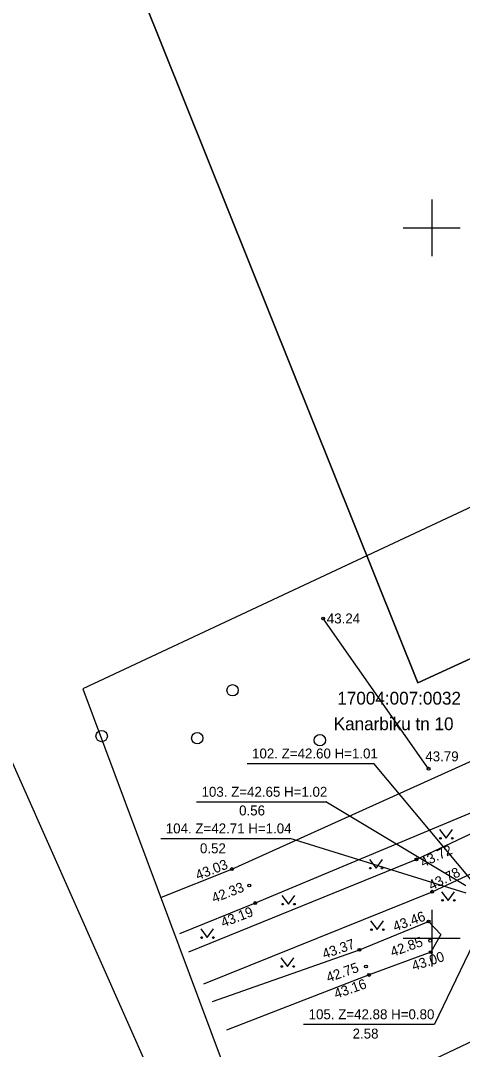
# Model space of a CAD drawing. Extents: x 642747 to 644424, y 6457048 to 6458238.
# Drawn here: x 643521.1 to 643552.2, y 6457442.2 to 6457514.6 of the extents above; entities that cross this region are included whole.
import ezdxf

# ---------------------------------------------------------------- set-up
doc = ezdxf.new("R2010")
doc.units = 0
for name, color, linetype in [('HALJASTUS', 7, 'Continuous'), ('JOONSIDE', 7, 'Continuous'), ('KOORDPUNKT', 7, 'Continuous'), ('KORGUS', 7, 'Continuous'), ('MOOTPIIR', 7, 'Continuous'), ('PIIR', 7, 'Continuous'), ('TEE', 7, 'Continuous'), ('VEEKOGU', 7, 'Continuous'), ('VORK', 7, 'Continuous'), ('VORMISTUS', 7, 'Continuous')]:
    doc.layers.add(name, color=color, linetype=linetype)

msp = doc.modelspace()

# ---------------------------------------------------------------- linework, layer by layer
at = {"layer": 'HALJASTUS'}
for p, q in [((643549.784, 6457461.931), (643542.364, 6457472.504)), ((643550.56, 6457457.643), (643551.024, 6457457.036)), ((643551.024, 6457457.036), (643551.469, 6457457.643)), ((643545.621, 6457455.54), (643546.085, 6457454.933)), ((643546.085, 6457454.933), (643546.53, 6457455.54)), ((643539.454, 6457453.001), (643539.918, 6457452.394)), ((643539.918, 6457452.394), (643540.363, 6457453.001)), ((643550.697, 6457453.264), (643551.161, 6457452.658)), ((643551.161, 6457452.658), (643551.606, 6457453.264)), ((643545.701, 6457451.213), (643546.165, 6457450.606)), ((643546.165, 6457450.606), (643546.61, 6457451.213)), ((643533.751, 6457450.653), (643534.215, 6457450.046)), ((643534.215, 6457450.046), (643534.66, 6457450.653)), ((643539.398, 6457448.619), (643539.861, 6457448.012)), ((643539.861, 6457448.012), (643540.307, 6457448.619))]:
    msp.add_line(p, q, dxfattribs=at)
for centre, radius in [((643535.994, 6457467.447), 0.4), ((643526.781, 6457464.228), 0.4), ((643533.508, 6457464.081), 0.4), ((643542.136, 6457463.935), 0.4), ((643550.622, 6457457.036), 0.055), ((643551.451, 6457457.036), 0.055), ((643545.683, 6457454.933), 0.055), ((643546.512, 6457454.933), 0.055), ((643539.517, 6457452.394), 0.055), ((643540.345, 6457452.394), 0.055), ((643550.76, 6457452.658), 0.055), ((643551.588, 6457452.658), 0.055), ((643533.814, 6457450.046), 0.055), ((643534.642, 6457450.046), 0.055), ((643545.764, 6457450.606), 0.055), ((643546.592, 6457450.606), 0.055), ((643539.46, 6457448.012), 0.055), ((643540.289, 6457448.012), 0.055)]:
    msp.add_circle(centre, radius, dxfattribs=at)
at = {"layer": 'KOORDPUNKT'}
for p, q in [((643537.014, 6457462.3), (643545.938, 6457462.3)), ((643552.787, 6457454.11), (643545.938, 6457462.3)), ((643533.46, 6457459.604), (643542.56, 6457459.604)), ((643552.412, 6457453.688), (643542.56, 6457459.604)), ((643530.943, 6457457.027), (643540.042, 6457457.027)), ((643552.422, 6457453.169), (643540.042, 6457457.027)), ((643553.504, 6457450.823), (643550.197, 6457443.946)), ((643540.993, 6457443.946), (643550.197, 6457443.946))]:
    msp.add_line(p, q, dxfattribs=at)
at = {"layer": 'KORGUS'}
for centre in [(643542.364, 6457472.504), (643549.784, 6457461.931), (643548.923, 6457455.546), (643535.943, 6457454.867), (643537.169, 6457453.715), (643550.034, 6457453.271), (643537.582, 6457452.477), (643549.783, 6457451.173), (643549.902, 6457449.827), (643544.915, 6457449.187), (643549.93, 6457449.018), (643545.378, 6457448.014), (643545.596, 6457447.416)]:
    msp.add_circle(centre, 0.1, dxfattribs=at)
at = {"layer": 'MOOTPIIR'}
msp.add_lwpolyline([(643525.446, 6457467.559), (643537.447, 6457435.458), (643944.848, 6457628.51), (644046.626, 6457529.09), (644067.022, 6457529.09), (644138.408, 6457598.401), (644075.1, 6457775.215), (644046.02, 6457752.582), (644092.466, 6457611.94), (644070.657, 6457576.375), (644041.981, 6457570.717), (643942.223, 6457662.862)], close=True, dxfattribs=at)
at = {"layer": 'PIIR'}
for points in [[(643435.34, 6457542.04), (643098.5, 6457289.43), (643172.06, 6457253.87), (643223.42, 6457347.01), (643584.12, 6457368.52), (643583, 6457371.27), (643552.96, 6457445.6), (643559.88, 6457465.04), (643557.62, 6457471.91), (643549.02, 6457467.97), (643522.25, 6457534.76), (643503.06, 6457583.41)], [(643584.66, 6457564.95), (643522.25, 6457534.76), (643549.02, 6457467.97), (643557.62, 6457471.91), (643559.88, 6457465.04), (643621.69, 6457493.88), (643604.64, 6457517.47), (643625.03, 6457526.9), (643614.96, 6457547.58), (643595.54, 6457570.21)]]:
    msp.add_lwpolyline(points, close=True, dxfattribs=at)
at = {"layer": 'TEE'}
for points in [[(643600.86, 6457480.184), (643599.201, 6457479.452), (643582.041, 6457471.211), (643565.611, 6457463.403), (643548.923, 6457455.546), (643532.88, 6457449.019)], [(643533.975, 6457446.78), (643550.034, 6457453.271), (643566.731, 6457461.052), (643583.357, 6457468.986), (643599.987, 6457476.97), (643601.811, 6457477.818)]]:
    msp.add_lwpolyline(points, dxfattribs=at)
at = {"layer": 'VEEKOGU'}
for points in [[(643530.994, 6457452.88), (643535.943, 6457454.867), (643555.789, 6457463.827)], [(643555.789, 6457463.827), (643557.795, 6457463.087), (643557.201, 6457460.671), (643537.582, 6457452.477), (643532.247, 6457450.315)], [(643534.578, 6457445.546), (643544.915, 6457449.187), (643549.783, 6457451.173), (643550.644, 6457450.268), (643549.93, 6457449.018), (643545.596, 6457447.416), (643535.56, 6457443.536)]]:
    msp.add_lwpolyline(points, dxfattribs=at)
at = {"layer": 'VORK'}
for p, q in [((643550, 6457502), (643550, 6457498)), ((643548, 6457500), (643552, 6457500)), ((643550, 6457452), (643550, 6457448)), ((643548, 6457450), (643552, 6457450))]:
    msp.add_line(p, q, dxfattribs=at)
at = {"layer": 'VORMISTUS'}
msp.add_line((643551.823, 6457391.833), (643493.811, 6457522.44), dxfattribs=at)

# ---------------------------------------------------------------- texts
at = {"layer": 'JOONSIDE'}
for s, p in [('0.56', (643536.452, 6457458.641)), ('0.52', (643533.698, 6457455.978)), ('2.58', (643544.436, 6457442.937))]:
    msp.add_text(s, height=0.7, dxfattribs=at).set_placement(p)
at = {"layer": 'KOORDPUNKT'}
for s, p in [('102. Z=42.60 H=1.01', (643537.364, 6457462.65)), ('103. Z=42.65 H=1.02', (643533.81, 6457459.954)), ('104. Z=42.71 H=1.04', (643531.293, 6457457.377)), ('105. Z=42.88 H=0.80', (643541.343, 6457444.296))]:
    msp.add_text(s, height=0.7, dxfattribs=at).set_placement(p)
at = {"layer": 'KORGUS'}
for s, p in [(' 43.24', (643542.364, 6457472.154)), (' 43.79', (643549.292, 6457462.45))]:
    msp.add_text(s, height=0.7, dxfattribs=at).set_placement(p)
for s, rotation, p in [(' 43.72', 25.22553, (643549.165, 6457454.861)), (' 43.03', 21.17085, (643533.304, 6457453.985)), (' 43.78', 26.67936, (643549.756, 6457453.236)), (' 42.33', 21.17085, (643534.442, 6457452.375)), (' 43.19', 21.17085, (643535.088, 6457450.652)), (' 43.46', 20.09278, (643547.183, 6457450.374)), (' 42.85', 19.76468, (643546.997, 6457448.591)), (' 43.37', 19.3562, (643542.203, 6457448.45)), (' 43.00', 18.09022, (643548.485, 6457447.614)), (' 42.75', 19.3562, (643542.483, 6457446.793)), (' 43.16', 19.3562, (643543.031, 6457445.644))]:
    msp.add_text(s, height=0.7, rotation=rotation, dxfattribs=at).set_placement(p)
at = {"layer": 'PIIR'}
for s, p in [('17004:007:0032', (643543.361, 6457466.442)), ('Kanarbiku tn 10', (643543.106, 6457464.642))]:
    msp.add_text(s, height=0.9, dxfattribs=at).set_placement(p)

doc.saveas('drawing.dxf')
